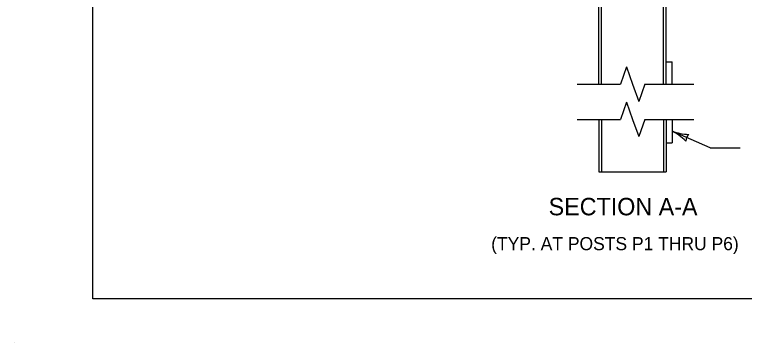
# Model space of a CAD drawing. Extents: x 49991.4 to 50021, y 49987.6 to 50011.4.
# Drawn here: x 49999.024 to 50002.376, y 49987.599 to 49989.103 of the extents above; entities that cross this region are included whole.
import ezdxf

# ---------------------------------------------------------------- set-up
doc = ezdxf.new("R2010")
doc.units = 0
for name, color, linetype in [('Level 1', 7, 'Continuous'), ('Level 2', 7, 'Continuous'), ('Level 3', 7, 'Continuous'), ('Level 6', 7, 'Continuous')]:
    doc.layers.add(name, color=color, linetype=linetype)

msp = doc.modelspace()

# ---------------------------------------------------------------- linework, layer by layer
at = {"layer": 'Level 1'}
for p, q in [((50001.7079, 49988.7839), (50001.7079, 49990.5649)), ((50001.7199, 49988.7839), (50001.7199, 49990.5649)), ((50002.005, 49988.7839), (50002.005, 49990.5649)), ((50002.0172, 49988.7839), (50002.0172, 49990.5649)), ((50002.0172, 49988.8871), (50002.0436, 49988.8871)), ((50002.0436, 49988.7839), (50002.0436, 49988.8871)), ((50001.7079, 49988.6223), (50001.7079, 49988.3821)), ((50001.7199, 49988.6223), (50001.7199, 49988.3821)), ((50002.005, 49988.6223), (50002.005, 49988.3821)), ((50002.0172, 49988.6223), (50002.0172, 49988.3821)), ((50002.0437, 49988.6223), (50002.0437, 49988.5154)), ((50002.0172, 49988.5154), (50002.0437, 49988.5154)), ((50001.7079, 49988.3821), (50002.0172, 49988.3821)), ((49999.0245, 49987.5988), (49999.0245, 49987.5988))]:
    msp.add_line(p, q, dxfattribs=at)
msp.add_lwpolyline([(49999.3835, 49998.9992), (50016.7501, 49998.9992), (50016.7501, 49987.7988), (49999.3835, 49987.7988)], close=True, dxfattribs=at)
at = {"layer": 'Level 3'}
for q in [(50002.0437, 49988.5689), (50002.3559, 49988.4914)]:
    msp.add_line((50002.2189, 49988.4914), q, dxfattribs=at)
for centre, radius, start, end in [((50001.9455, 49988.3694), 0.2223, 43.6075, 63.791), ((50002.1273, 49988.7863), 0.233, 248.9788, 268.2287), ((50002.161, 49988.517), 0.0548, 138.2903, 174.0127)]:
    msp.add_arc(centre, radius, start, end, dxfattribs=at)
at = {"layer": 'Level 6'}
for p, q in [((50001.8347, 49988.863), (50001.8068, 49988.7839)), ((50001.8347, 49988.863), (50001.8625, 49988.7839)), ((50001.6079, 49988.7839), (50001.8068, 49988.7839)), ((50001.8625, 49988.7839), (50001.8908, 49988.7049)), ((50001.9187, 49988.7839), (50001.8908, 49988.7049)), ((50001.9187, 49988.7839), (50002.1436, 49988.7839)), ((50001.8347, 49988.7014), (50001.8068, 49988.6223)), ((50001.8347, 49988.7014), (50001.8625, 49988.6223)), ((50001.6079, 49988.6223), (50001.8068, 49988.6223)), ((50001.8625, 49988.6223), (50001.8908, 49988.5433)), ((50001.9187, 49988.6223), (50001.8908, 49988.5433)), ((50001.9187, 49988.6223), (50002.1437, 49988.6223))]:
    msp.add_line(p, q, dxfattribs=at)

# ---------------------------------------------------------------- texts
at = {"layer": 'Level 2'}
for s, height, p in [('SECTION A-A', 0.08, (50001.477, 49988.182)), ('(TYP. AT POSTS P1 THRU P6)', 0.06, (50001.2131, 49988.022))]:
    msp.add_text(s, height=height, dxfattribs=at).set_placement(p)

doc.saveas('drawing.dxf')
